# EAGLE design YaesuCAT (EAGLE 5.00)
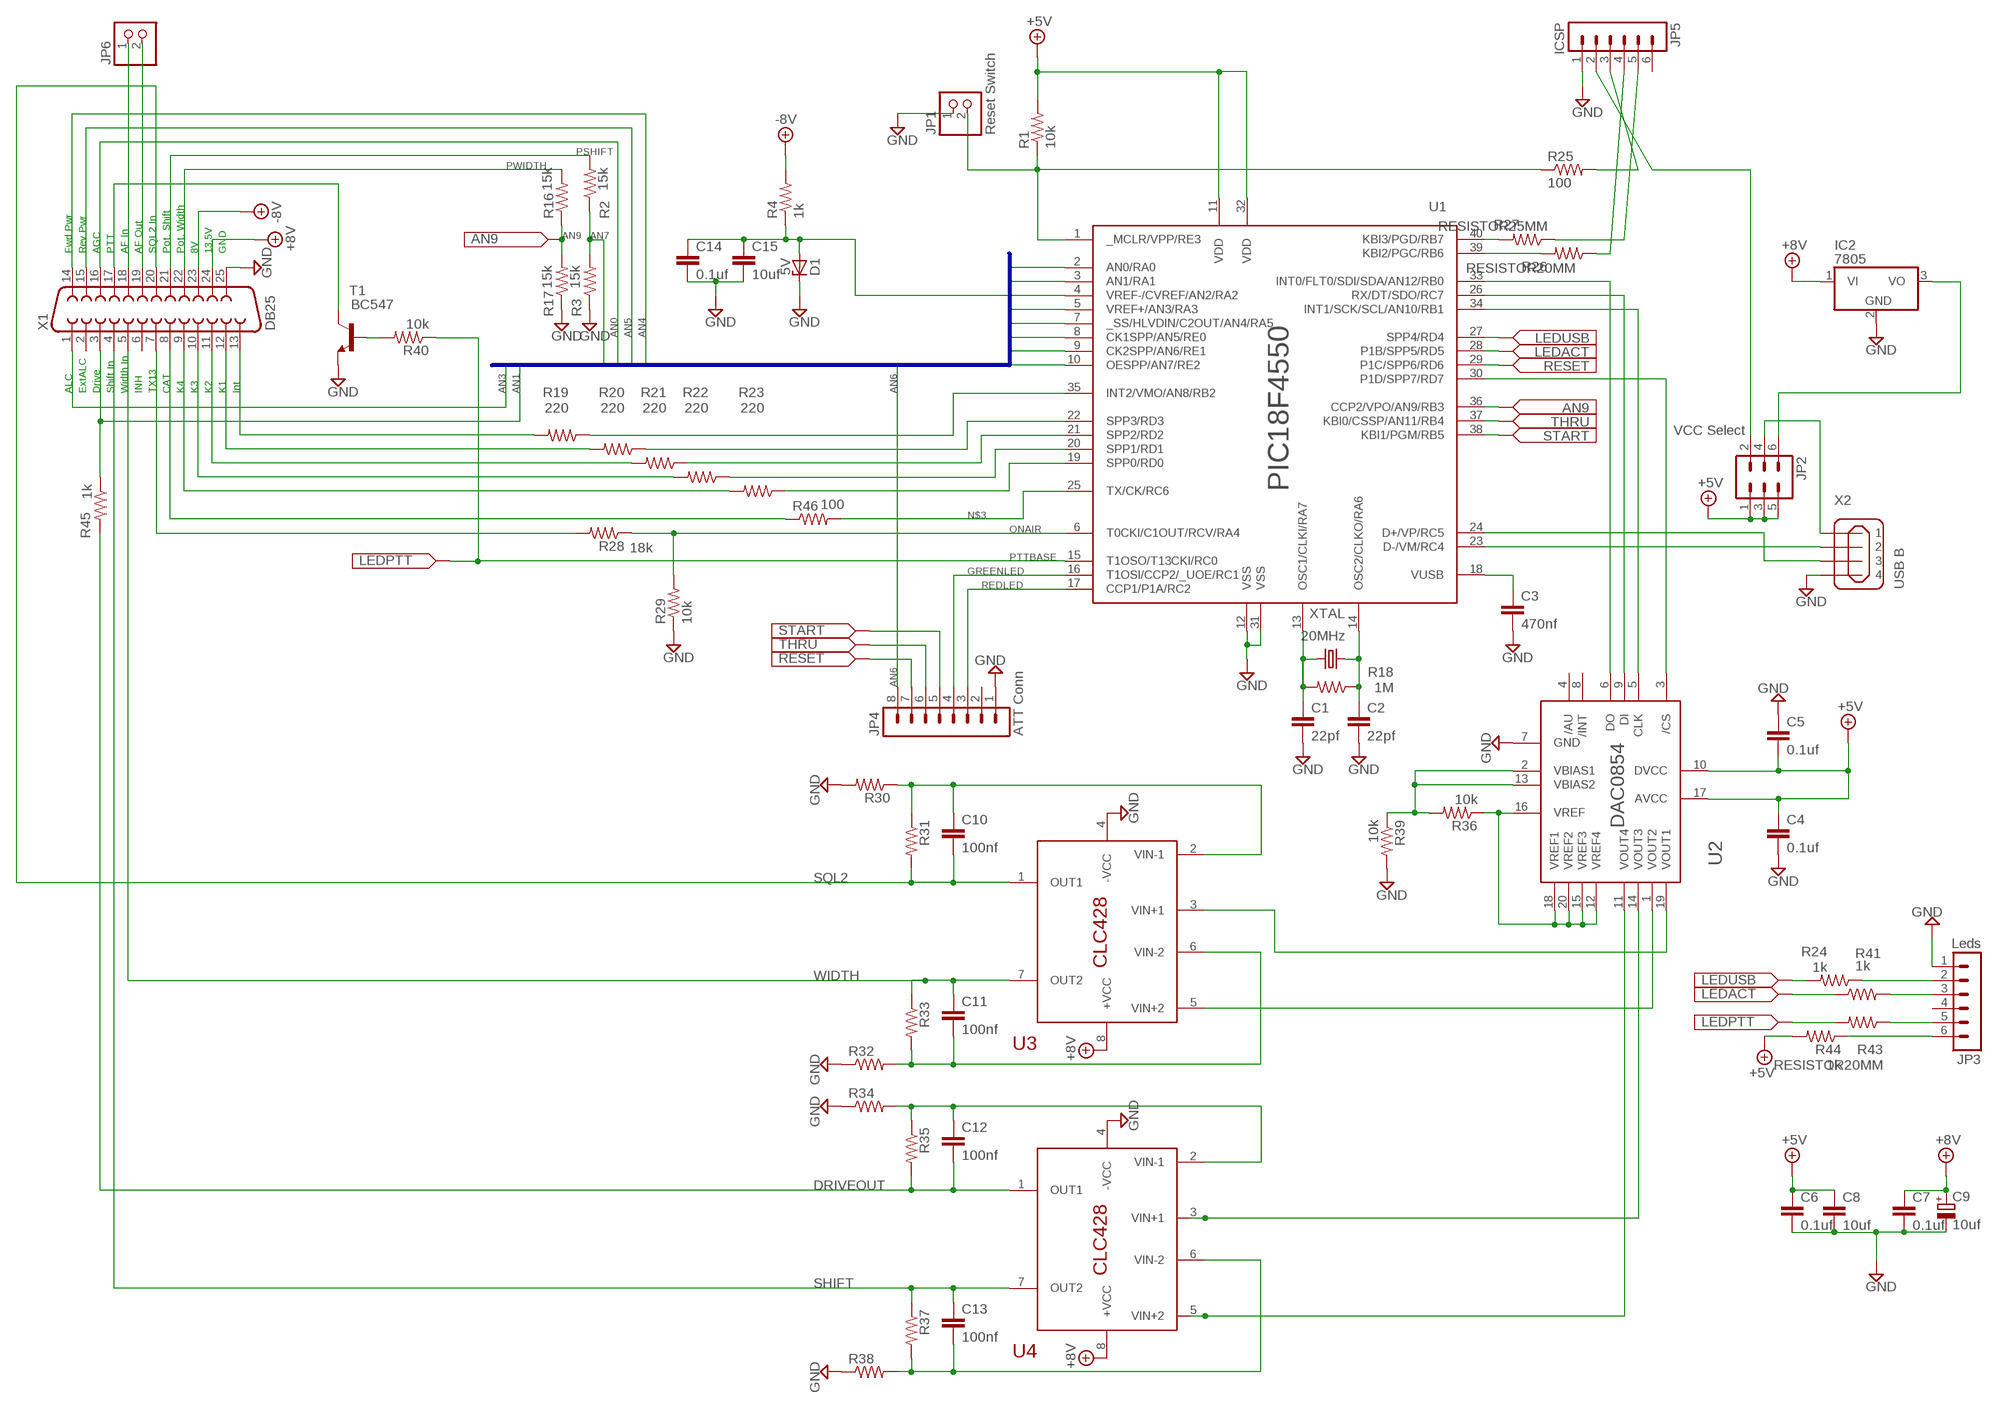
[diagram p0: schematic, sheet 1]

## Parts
C1  22pf  C-EU050-035X075  [C050-035X075]
C2  22pf  C-EU075-032X103  [C075-032X103]
C3  470nf  C-EU050-035X075  [C050-035X075]
C4  0.1uf  C-EU025-030X050  [C025-030X050]
C5  0.1uf  C-EU050-035X075  [C050-035X075]
C6  0.1uf  C-EU050-035X075  [C050-035X075]
C7  0.1uf  C-EU050-035X075  [C050-035X075]
C8  10uf  C-EU050-035X075  [C050-035X075]
C9  10uf  CPOL-EUE3.5-8  [E3,5-8]
C10  100nf  C-EU050-035X075  [C050-035X075]
C11  100nf  C-EU050-035X075  [C050-035X075]
C12  100nf  C-EU050-035X075  [C050-035X075]
C13  100nf  C-EU050-035X075  [C050-035X075]
C14  0.1uf  C-EU050-035X075  [C050-035X075]
C15  10uf  C-EU050-035X075  [C050-035X075]
D1  5V  ZENER-DIODEZD-7.5  [ZDIO-7.5]
IC2  7805  7805TV  [TO220V]
JP1  Reset Switch  PINHD-1X2  [1X02]
JP2  VCC Select  MA03-2  [MA03-2]
JP3  Leds  MA06-1  [MA06-1]
JP4  ATT Conn  MA08-1  [MA08-1]
JP5  ICSP  MA06-1  [MA06-1]
JP6  PINHD-1X2  [1X02]
R1  10k  R-US_0207/12  [0207/12]
R2  15k  R-US_0207/15  [0207/15]
R3  15k  R-US_0207/10  [0207/10]
R4  1k  R-US_0207/12  [0207/12]
R16  15k  R-US_0207/15  [0207/15]
R17  15k  R-US_0207/10  [0207/10]
R18  1M  R-US_0207/2V  [0207/2V]
R19  220  R-US_0207/10  [0207/10]
R20  220  R-US_0207/10  [0207/10]
R21  220  R-US_0207/10  [0207/10]
R22  220  R-US_0207/10  [0207/10]
R23  220  R-US_0207/15  [0207/15]
R24  1k  R-US_0207/10  [0207/10]
R25  100  R-US_0207/12  [0207/12]
R26  RESISTOR20MM  [R207/20MM]
R27  RESISTOR25MM  [R207/25MM]
R28  18k  R-US_0207/5V  [0207/5V]
R29  10k  R-US_0207/5V  [0207/5V]
R30  R-US_0207/10  [0207/10]
R31  R-US_0207/2V  [0207/2V]
R32  R-US_0207/2V  [0207/2V]
R33  R-US_0207/10  [0207/10]
R34  R-US_0207/10  [0207/10]
R35  R-US_0207/10  [0207/10]
R36  10k  R-US_0204/5  [0204/5]
R37  R-US_0207/2V  [0207/2V]
R38  R-US_0207/5V  [0207/5V]
R39  10k  R-US_0207/7  [0207/7]
R40  10k  R-US_0207/15  [0207/15]
R41  1k  R-US_0207/10  [0207/10]
R43  RESISTOR20MM  [R207/20MM]
R44  1k  R-US_0207/10  [0207/10]
R45  1k  R-US_0207/15  [0207/15]
R46  100  R-US_0207/10  [0207/10]
T1  BC547  [TO92]
U1  PIC18F4550  [DIP40]
U2  DAC0854  [DIP20]
U3  CLC428  [DIP8]
U4  CLC428  [DIP8]
X1  DB25  F25HP  [F25HP]
X2  USB B  MINI-USB_SHIELD4P-85-32004-00X  [85-32004-00X]
XTAL  20MHz  CRYSTALHC49U70  [HC49U70]

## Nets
+5V: C4.1 C5.2 C6.1 C8.1 JP2.1 JP2.3 JP2.5 R1.2 R44.2 U1.11(VDD) U1.32(VDD) U2.10(DVCC) U2.17(AVCC)
+8V: C7.1 C9.+ IC2.1(VI) U3.8(+VCC) U4.8(+VCC) X1.24
-8V: R4.2 X1.23
-VREF: C14.1 C15.1 D1.A R4.1 U1.4(VREF-/CVREF/AN2/RA2)
AN0: U1.2(AN0/RA0) X1.16
AN1: R45.1 U1.3(AN1/RA1) X1.3
AN3: U1.5(VREF+/AN3/RA3) X1.1
AN4: U1.7(_SS/HLVDIN/C2OUT/AN4/RA5) X1.14
AN5: U1.8(CK1SPP/AN5/RE0) X1.15
AN6: JP4.8 U1.9(CK2SPP/AN6/RE1)
AN7: R2.1 R3.2 U1.10(OESPP/AN7/RE2)
AN9: R16.1 R17.2 U1.36(CCP2/VPO/AN9/RB3)
CAT: R46.1 X1.8
CSDAC: U1.30(P1D/SPP7/RD7) U2.3(/CS)
D+: U1.24(D+/VP/RC5) X2.3
D-: U1.23(D-/VM/RC4) X2.2
DRIVEOUT: C12.2 R35.2 R45.2 U4.1(OUT1)
GND: C1.2 C2.2 C3.2 C4.2 C5.1 C6.2 C7.2 C8.2 C9.- C14.2 C15.2 D1.C IC2.2(GND) JP1.1 JP3.1 JP4.1 JP5.1 R3.1 R17.1 R29.1 R30.2 R32.1 R34.1 R38.1 R39.2 T1.1(E) U1.12(VSS) U1.31(VSS) U2.7(GND) U3.4(-VCC) U4.4(-VCC) X1.25 X2.4
GREENLED: JP4.4 U1.16(T1OSI/CCP2/_UOE/RC1)
INT: R19.2 X1.13
K1: R20.2 X1.12
K2: R21.2 X1.11
K3: R22.2 X1.10
K4: R23.2 X1.9
LEDACT: R41.1 U1.28(P1B/SPP5/RD5)
LEDUSB: R24.2 U1.27(SPP4/RD4)
N$1: JP1.2 R1.1 R25.1 U1.1(_MCLR/VPP/RE3)
N$2: JP5.4 R26.P$1
N$3: R46.2 U1.25(TX/CK/RC6)
N$5: JP6.1 X1.18
N$6: JP6.2 X1.19
N$10: R20.1 U1.22(SPP3/RD3)
N$11: R27.P$2 U1.40(KBI3/PGD/RB7)
N$12: R26.P$2 U1.39(KBI2/PGC/RB6)
N$13: R21.1 U1.21(SPP2/RD2)
N$14: JP5.5 R27.P$1
N$17: R19.1 U1.35(INT2/VMO/AN8/RB2)
N$20: JP5.3 R25.2
N$22: JP3.2 R24.1
N$23: JP3.3 R41.2
N$25: JP3.5 R43.P$1
N$30: JP3.6 R44.1
N$34: C1.1 R18.2 U1.13(OSC1/CLKI/RA7) XTAL.2
N$35: C2.1 R18.1 U1.14(OSC2/CLKO/RA6) XTAL.1
N$36: JP2.2 JP5.2
N$37: C3.1 U1.18(VUSB)
N$41: C13.2 R37.2 R38.2 U4.6(VIN-2)
N$42: C12.1 R34.2 R35.1 U4.2(VIN-1)
N$43: C11.2 R32.2 R33.2 U3.6(VIN-2)
N$44: C10.1 R30.1 R31.1 U3.2(VIN-1)
N$49: R40.2 T1.2(B)
N$50: U2.19(VOUT1) U3.3(VIN+1)
N$51: U2.1(VOUT2) U3.5(VIN+2)
N$52: U2.14(VOUT3) U4.3(VIN+1)
N$53: U2.11(VOUT4) U4.5(VIN+2)
N$54: U1.34(INT1/SCK/SCL/AN10/RB1) U2.5(CLK)
N$55: U1.26(RX/DT/SDO/RC7) U2.9(DI)
N$56: U1.33(INT0/FLT0/SDI/SDA/AN12/RB0) U2.6(DO)
N$58: R36.1 U2.12(VREF4) U2.15(VREF3) U2.16(VREF) U2.18(VREF1) U2.20(VREF2)
N$60: IC2.3(VO) JP2.6
ONAIR: R28.1 R29.2 U1.6(T0CKI/C1OUT/RCV/RA4)
PSHIFT: R2.2 X1.21
PTT: T1.3(C) X1.17
PTTBASE: R40.1 R43.P$2 U1.15(T1OSO/T13CKI/RC0) ; supply symbol labelled LEDPTT
PWIDTH: R16.2 X1.22
RD0: R23.1 U1.19(SPP0/RD0)
RD1: R22.1 U1.20(SPP1/RD1)
REDLED: JP4.3 U1.17(CCP1/P1A/RC2)
RESET: JP4.7 U1.29(P1C/SPP6/RD6)
SHIFT: C13.1 R37.1 U4.7(OUT2) X1.4
SQL2: C10.2 R31.2 U3.1(OUT1) X1.20
START: JP4.5 U1.38(KBI1/PGM/RB5)
THRU: JP4.6 U1.37(KBI0/CSSP/AN11/RB4)
TX13: R28.2 X1.7
USB+5V: JP2.4 X2.1
VBIAS: R36.2 R39.1 U2.2(VBIAS1) U2.13(VBIAS2)
WIDTH: C11.1 R33.1 U3.7(OUT2) X1.5
Unconnected: JP3.4 JP4.2 JP5.6 U2.4(/AU) U2.8(/INT) X1.2 X1.6 X2.M1(S1) X2.M2(S2)

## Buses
AN[0..7]

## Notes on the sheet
- Fwd Pwr | Rev Pwr | AGC | PTT | AF In | AF Out | SQL2 In | Pot. Shift | Pot. Width | 8V | 13.5V | GND
- ALC | ExtALC | Drive | Shift In | Width In | INH | TX13 | CAT | K4 | K3 | K2 | K1 | Int

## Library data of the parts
C1-C8 C10-C15 = resistor:C-EU: CAPACITOR, European symbol
C9 = resistor:CPOL-EU: POLARIZED CAPACITOR, European symbol
D1 = diode:ZENER-DIODE: Z-Diode
IC2 = linear:78*: Positive VOLTAGE REGULATOR Source: http://cache.national.com/ds/LM/LM78L05.pdf http://www.fairchildsemi.com/ds/LM/LM7805.pdf
JP1 JP6 = pinhead:PINHD-1X2: PIN HEADER
JP2 = con-lstb:MA03-2: PIN HEADER
JP3 JP5 = con-lstb:MA06-1: PIN HEADER
JP4 = con-lstb:MA08-1: PIN HEADER
R1-R4 R16-R25 R28-R41 R44-R46 = resistor:R-US_: RESISTOR, American symbol
R26 R27 R43 = components:RESISTOR
T1 = transistor:BC547: NPN TRANSISTOR
U1 = components:PIC18F4550: PIC18F4550 DIP-40 Specially arranged for schematics for the Yaesu FT-757GX Enhanced CAT interface schematics.
U2 = components:DAC0854: Quad 8-bit DAC. Controlled by SPI.
U3 U4 = components:CLC428: Dual wideband Op Amp
X1 = con-subd:F25: SUB-D
X2 = con-cypressindustries:MINI-USB_SHIELD4P-: MINI USB 4 Pol. Source: www.cypressindustries.com
XTAL = crystal:CRYSTAL: CRYSTAL

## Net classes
0 default: width 0.508 mm, drill 0.127 mm, clearance 0.381 mm

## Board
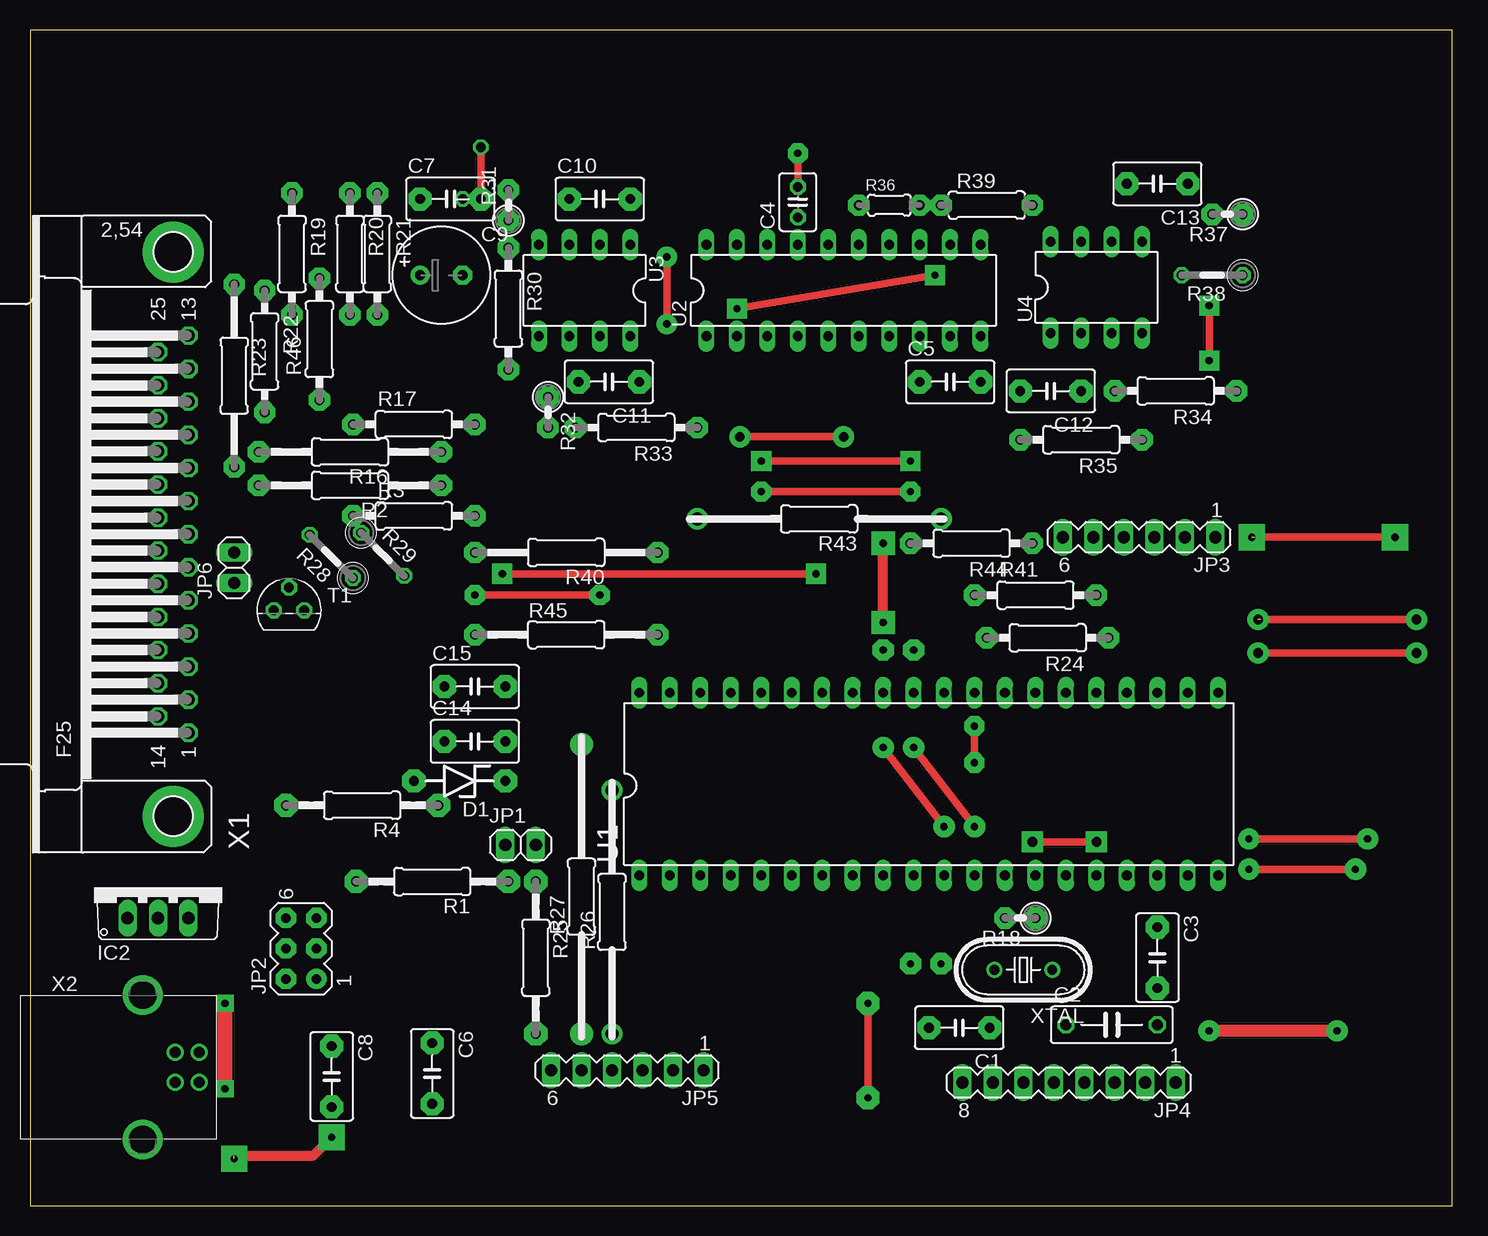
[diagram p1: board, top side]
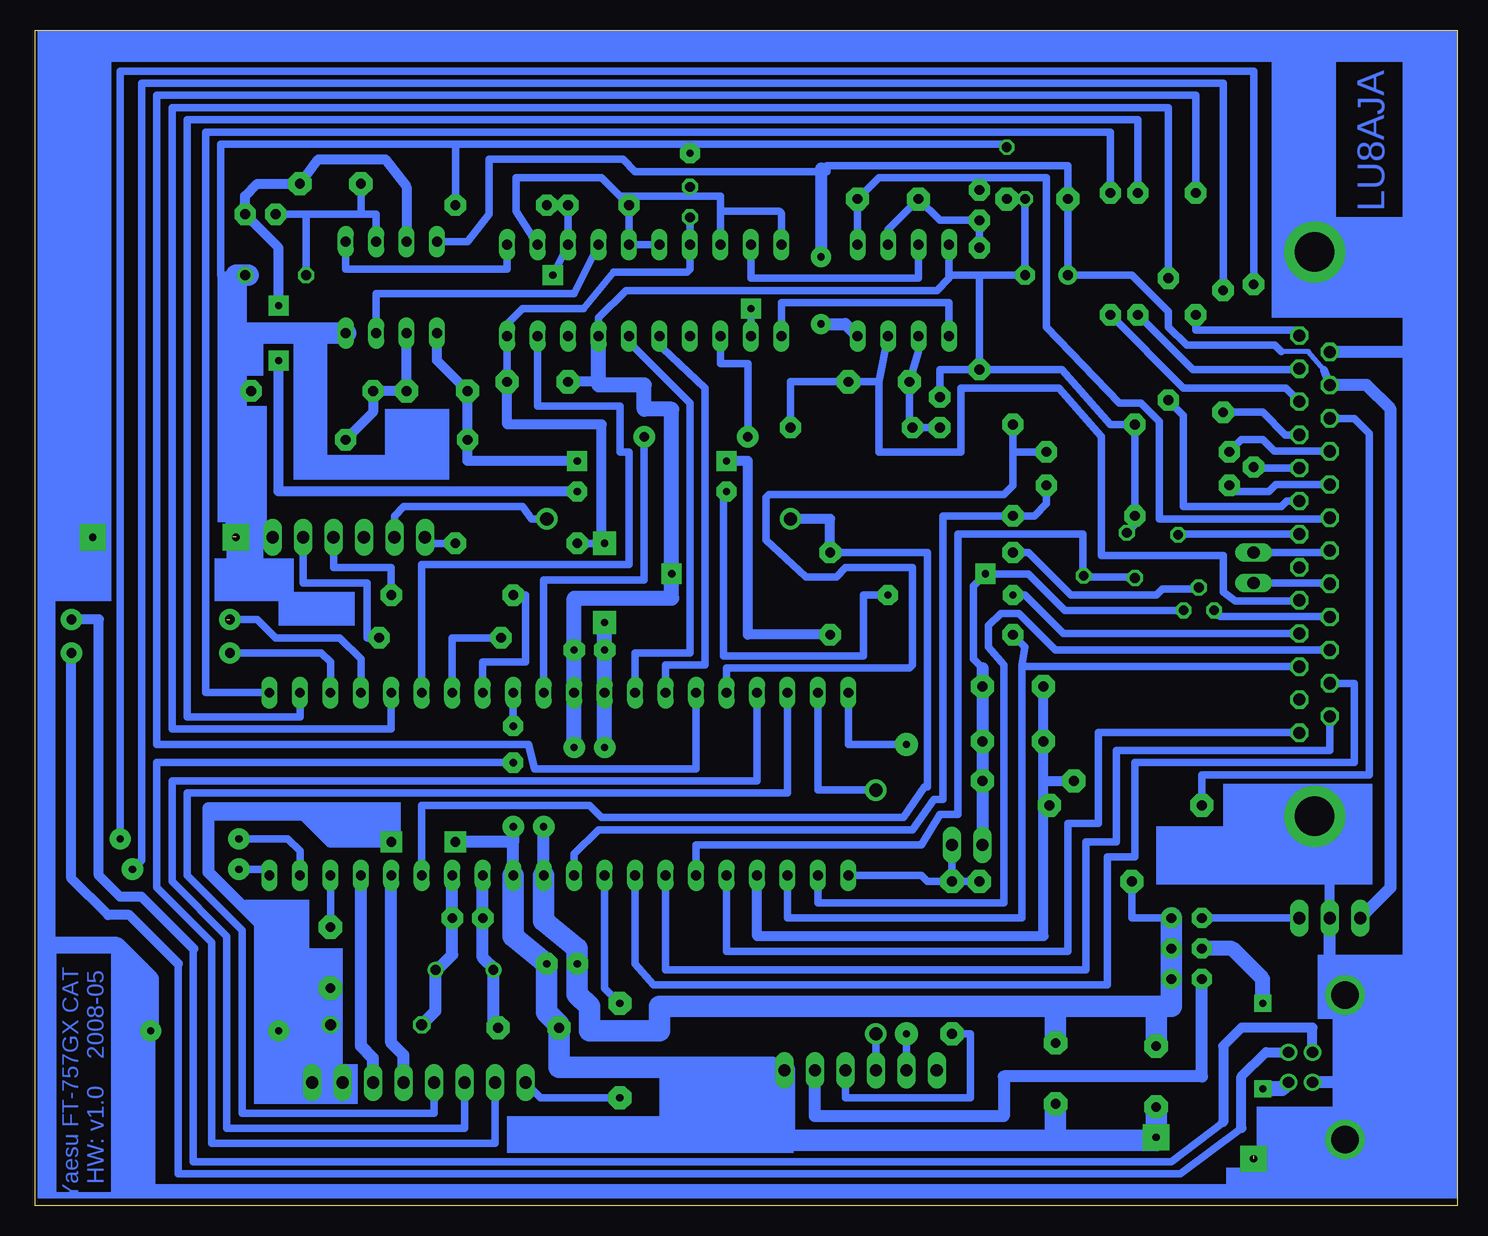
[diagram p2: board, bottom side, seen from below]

Size 118.54 x 98.03 mm. Coordinates in mm from the lower left corner, seen from the top.
Outline: 0,0 118.54,0 118.54,98.03 0,98.03 0,0
Copper layers (1*16): Top 0.035mm / dielectric 1.5mm / Bottom 0.035mm
Design rules "default *": minimum track width 20mil, minimum drill 5mil, track to track 8mil, track to pad 8mil, pad to pad 8mil, via to via 8mil, smd to smd 8mil, copper to edge 40mil, drill to drill 8mil, minimum pad ring 10mil, minimum via ring 8mil, stop-mask expansion 4mil, vias tented up to drill 20mil, thermal gap 10mil

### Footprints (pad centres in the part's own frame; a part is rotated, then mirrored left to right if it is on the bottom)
C050-035X075 = drill 0.813 pad 1.93 octagon: 1 -2.54,0; 2 2.54,0
C075-032X103 = drill 0.914 octagon: 1 -3.81,0; 2 3.81,0
C025-030X050 = drill 0.813 octagon: 1 -1.27,0; 2 1.27,0
E3,5-8 = drill 0.813 pad 1.6 round: + -1.778,0 | drill 0.813 pad 1.6 octagon: - 1.778,0
ZDIO-7.5 = drill 0.813 pad 1.93 octagon: A 3.81,0; C -3.81,0
TO220V = drill 1.016 long: 1 -2.54,-2.54; 2 0,-2.54; 3 2.54,-2.54
1X02 = drill 1.016 long: 1 -1.27,0; 2 1.27,0
MA03-2 = drill 0.8 pad 1.676 round: 1 -2.54,-1.27 | drill 0.8 pad 1.676 octagon: 2 -2.54,1.27; 3 0,-1.27; 4 0,1.27; 5 2.54,-1.27; 6 2.54,1.27
MA06-1 = drill 1.016 long: 1 -6.35,0; 2 -3.81,0; 3 -1.27,0; 4 1.27,0; 5 3.81,0; 6 6.35,0
MA08-1 = drill 1.016 long: 1 -8.89,0; 2 -6.35,0; 3 -3.81,0; 4 -1.27,0; 5 1.27,0; 6 3.81,0; 7 6.35,0; 8 8.89,0
0207/12 = drill 0.813 pad 1.93 octagon: 1 -6.35,0; 2 6.35,0
0207/15 = drill 0.813 pad 1.778 octagon: 1 -7.62,0; 2 7.62,0
0207/10 = drill 0.813 pad 1.778 octagon: 1 -5.08,0; 2 5.08,0
0207/2V = drill 0.813 pad 1.778 octagon: 1 -1.27,0; 2 1.27,0
R207/20MM = drill 1.1 pad 1.778 round: P$1 -10.16,0; P$2 10.16,0
R207/25MM = drill 0.6 pad 1.93 round: P$1 -11.43,0; P$2 12.7,0
0207/5V = drill 0.813 octagon: 1 -2.54,0; 2 2.54,0
0204/5 = drill 0.813 pad 1.778 octagon: 1 -2.54,0; 2 2.54,0
0207/7 = drill 0.813 pad 1.778 octagon: 1 -3.81,0; 2 3.81,0
TO92 = drill 0.813 octagon: 1 1.27,0; 2 0,1.905; 3 -1.27,0
DIP40 = drill 0.813 long: 1 -24.13,-8.89; 2 -21.59,-8.89; 3 -19.05,-8.89; 4 -16.51,-8.89; 5 -13.97,-8.89; 6 -11.43,-8.89; 7 -8.89,-8.89; 8 -6.35,-8.89; 9 -3.81,-8.89; 10 -1.27,-8.89; 11 1.27,-8.89; 12 3.81,-8.89; 13 6.35,-8.89; 14 8.89,-8.89; 15 11.43,-8.89; 16 13.97,-8.89; 17 16.51,-8.89; 18 19.05,-8.89; 19 21.59,-8.89; 20 24.13,-8.89; 21 24.13,6.35; 22 21.59,6.35; 23 19.05,6.35; 24 16.51,6.35; 25 13.97,6.35; 26 11.43,6.35; 27 8.89,6.35; 28 6.35,6.35; 29 3.81,6.35; 30 1.27,6.35; 31 -1.27,6.35; 32 -3.81,6.35; 33 -6.35,6.35; 34 -8.89,6.35; 35 -11.43,6.35; 36 -13.97,6.35; 37 -16.51,6.35; 38 -19.05,6.35; 39 -21.59,6.35; 40 -24.13,6.35
DIP20 = drill 0.813 long: 1 -11.43,-3.81; 2 -8.89,-3.81; 3 -6.35,-3.81; 4 -3.81,-3.81; 5 -1.27,-3.81; 6 1.27,-3.81; 7 3.81,-3.81; 8 6.35,-3.81; 9 8.89,-3.81; 10 11.43,-3.81; 11 11.43,3.81; 12 8.89,3.81; 13 6.35,3.81; 14 3.81,3.81; 15 1.27,3.81; 16 -1.27,3.81; 17 -3.81,3.81; 18 -6.35,3.81; 19 -8.89,3.81; 20 -11.43,3.81
DIP8 = drill 0.813 long: 1 -3.81,-3.81; 2 -1.27,-3.81; 3 1.27,-3.81; 4 3.81,-3.81; 5 3.81,3.81; 6 1.27,3.81; 7 -1.27,3.81; 8 -3.81,3.81
F25HP = drill 1.016 octagon: 1 -16.561,-1.27; 2 -13.792,-1.27; 3 -11.049,-1.27; 4 -8.28,-1.27; 5 -5.512,-1.27; 6 -2.769,-1.27; 7 0,-1.27; 8 2.769,-1.27; 9 5.512,-1.27; 10 8.28,-1.27; 11 11.049,-1.27; 12 13.792,-1.27; 13 16.561,-1.27; 14 -15.189,1.27; 15 -12.421,1.27; 16 -9.652,1.27; 17 -6.909,1.27; 18 -4.14,1.27; 19 -1.372,1.27; 20 1.372,1.27; 21 4.14,1.27; 22 6.909,1.27; 23 9.652,1.27; 24 12.421,1.27; 25 15.189,1.27 | drill 3.302 pad 5.08 round: G1 -23.52,0; G2 23.52,0
85-32004-00X = drill 0.92 pad 1.27 round: 1 4.71,-1.25; 2 4.71,1.25; 3 2.71,1.25; 4 2.71,-1.25 | drill 2.3 pad 3 round: M1 0,6.02; M2 0,-6.02
HC49U70 = drill 0.813 round: 1 -2.413,0; 2 2.413,0

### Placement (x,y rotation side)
C1  77.43,14.85 180 top
C2  90.13,15.11 0 top
C3  93.94,20.7 270 top
C4  63.97,83.69 90 top
C5  76.67,68.7 0 top
C6  33.49,11.04 270 top
C7  35.01,83.94 0 top
C8  25.11,10.79 270 top
C9  34.25,77.59 0 top
C10  47.46,83.94 0 top
C11  48.22,68.7 180 top
C12  85.05,67.94 180 top
C13  93.94,85.21 180 top
C14  37.05,38.73 0 top
C15  37.05,43.3 0 top
D1  35.78,35.43 180 top
IC2  10.63,26.54 0 top
JP1  40.86,30.09 0 top
JP2  22.57,21.46 90 top
JP3  92.42,55.75 180 top
JP4  86.58,10.28 180 top
JP5  49.75,11.3 180 top
JP6  16.98,53.21 90 top
R1  33.49,27.05 180 top
R2  26.63,60.07 180 top
R3  31.97,57.53 0 top
R4  27.65,33.4 180 top
R16  26.63,62.86 180 top
R17  31.97,65.15 0 top
R18  82.51,24 180 top
R19  21.81,79.37 270 top
R20  26.63,79.37 270 top
R21  28.92,79.37 270 top
R22  19.52,71.24 270 top
R23  16.98,69.21 270 top
R24  84.8,47.37 180 top
R25  42.13,20.7 270 top
R26  48.48,24.51 90 top
R27  45.94,25.78 90 top
R28  25.08,54.15 135 top
R29  29.35,54.33 315 top
R30  39.84,74.8 270 top
R31  39.84,83.43 90 top
R32  43.14,66.16 270 top
R33  50.51,64.89 180 top
R34  95.47,67.94 180 top
R35  87.59,63.88 180 top
R36  71.59,83.43 0 top
R37  99.78,82.67 180 top
R38  98.51,77.59 180 top
R39  79.72,83.43 0 top
R40  44.67,54.48 180 top
R41  83.78,50.92 0 top
R43  65.75,57.27 180 top
R44  78.45,55.24 180 top
R45  44.67,47.62 0 top
R46  24.09,72.26 90 top
T1  21.55,49.65 0 top
U1  74.89,36.44 0 top
U2  67.78,76.32 0 top
U3  46.19,76.32 180 top
U4  88.86,76.58 0 top
X1  11.9,56 90 top
X2  9.36,11.55 0 top
XTAL  82.77,19.68 180 top

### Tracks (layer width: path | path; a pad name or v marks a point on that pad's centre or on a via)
+5V  (via drill 0.6 pad 1.78, 0.6 pad 1.93)
  Top 0.61: v76.16,31.62 v71.08,38.22
  Top 0.813: v71.08,48.64 v71.08,55.24
  Bottom 0.61: C5.2 U2.10 79.21,73.53 77.94,74.8 72.86,74.8 70.32,77.85 64.22,77.85 63.97,78.1 U2.17 C4.1 | v71.08,55.24 R44.2 | R1.2 27.14,24 JP2.5
  Bottom 0.813: v71.08,55.24 71.34,55.24 71.34,65.15 79.21,65.15 C5.2
  Bottom 1.016: U1.11 v76.16,31.62
  Bottom 1.27: v71.08,38.22 U1.32 v71.08,46.35 v71.08,48.64
  Bottom 1.778: JP2.5 JP2.3 JP2.1 | JP2.1 23.84,18.66 | JP2.1 23.84,16.63 25.11,16.63 | 25.11,16.63 33.49,16.63 | 33.49,16.63 66.51,16.63 66.51,14.6 72.35,14.6 72.35,16.63 73.37,17.65 v73.37,20.19 73.37,21.46 76.16,23.74 U1.11 | C8.1 25.11,16.63 | 33.49,16.63 C6.1
+8V  (via drill 0.6 pad 1.68)
  Top 0.61: v53.05,79.12 v53.05,73.53
  Bottom 0.406: 11.14,69.72 12.41,71.24 14.69,71.24
  Bottom 0.61: U4.8 82.51,80.39 80.73,82.67 80.73,87.24 69.56,87.24 68.54,86.23 53.05,86.23 52.54,86.23 52.54,86.74 32.47,86.74 C7.1 C9.+ 27.14,77.59 24.09,74.54 24.09,73.27 22.57,71.75 15.2,71.75 14.69,71.24 | X1.24 11.14,69.72
  Bottom 1.016: U3.8 51.02,73.53 v53.05,73.53 | 53.05,86.48 53.05,86.23 v53.05,79.12 | IC2.1 5.55,26.54 5.55,66.42 7.58,68.45 10.63,68.45 X1.24
-8V
  Bottom 0.61: R4.2 21.3,35.94 7.33,35.94 7.33,64.38 8.6,65.65 X1.23
-VREF
  Bottom 0.813: U1.4 58.38,22.47 34.51,22.47 34.51,33.4 | C14.1 34.51,38.48 | C14.1 C15.1 | 34.51,35.43 C14.1 | 34.51,35.43 D1.A | 34.51,33.4 34.51,35.43 | 34.51,33.4 R4.1
AN0
  Bottom 0.61: U1.2 53.3,25.27 37.81,25.27 37.81,45.08 39.08,46.6 39.08,48.38 38.06,49.4 36.54,49.4 33.49,46.35 X1.16
AN1
  Bottom 0.61: U1.3 55.84,24 36.28,24 36.28,45.08 | 36.28,45.08 36.03,46.6 R45.1 | X1.3 35.9,44.95 36.28,45.08
AN3
  Bottom 0.61: U1.5 60.92,21.2 32.47,21.2 32.47,31.87 29.93,31.87 29.93,39.49 13.17,39.49 X1.1
AN4
  Bottom 0.61: U1.7 66,19.68 30.95,19.68 30.95,30.35 28.41,30.35 28.41,37.97 10.63,37.97 X1.14
AN5
  Bottom 0.61: U1.8 68.54,20.19 67.02,18.41 29.17,18.41 29.17,29.08 26.89,29.08 26.89,36.95 8.6,36.95 8.6,43.56 10.63,43.56 X1.15
AN6  (via drill 0.6 pad 1.93)
  Top 0.61: v69.81,9.01 v69.81,16.89
  Bottom 0.61: JP4.8 76.42,9.01 v69.81,9.01 | v69.81,16.89 71.08,18.16 U1.9
AN7
  Bottom 0.61: R2.1 34.25,58.54 35.27,57.53 R3.2 42.89,57.53 42.89,33.9 43.65,33.9 45.43,31.36 71.59,31.36 73.62,29.33 U1.10
AN9
  Bottom 0.61: 37.05,62.86 R17.2 | 37.05,62.86 R16.1 | 37.05,62.86 37.05,60.07 37.81,59.3 57.37,59.3 57.62,59.05 57.62,55.49 54.32,52.45 51.78,52.45 51.02,53.21 45.43,53.21 45.43,45.08 45.68,44.83 60.92,44.83 U1.36
CAT
  Bottom 0.61: X1.8 14.21,58.77 14.69,58.29 22.82,58.29 22.82,65.91 R46.1
CSDAC  (via drill 0.8 pad 1.78)
  Top 0.61: v67.78,64.13 v59.14,64.13
  Bottom 0.61: U1.30 76.16,52.19 67.78,52.19 v67.78,64.13 | U2.3 61.43,70.23 59.14,70.23 v59.14,64.13
D+  (via drill 0.8 pad 1.78)  (1 unrouted)
  Top 0.61: v115.53,48.89 102.58,48.89
  Bottom 0.61: v102.32,48.89 100.04,48.89 98.51,47.37 93.18,47.37 91.4,45.59 U1.24 | 19.52,6.98 23.84,3.68 105.37,3.68 105.37,21.46
  Bottom 0.813: X2.3 12.09,14.85 18,14.85 19.52,13.33 19.52,6.98 | 105.37,21.46 109.69,25.78 111.47,25.78 113.25,27.55 113.25,48.89 v115.53,48.89
D-  (via drill 0.8 pad 1.78)
  Top 0.61: v115.53,46.1 v102.32,46.1
  Bottom 0.61: v102.32,46.1 94.7,46.1 93.94,45.33 U1.23 93.94,42.54 | 18,6.47 23.08,2.66 106.64,2.66 106.64,20.19
  Bottom 0.813: X2.2 15.96,12.82 18,10.79 18,6.47 | 106.64,20.19 110.71,24.25 112.48,24.25 115.53,27.3 v115.53,46.1
DRIVEOUT  (via drill 0.6 pad 1.68)
  Top 0.61: v60.92,62.1 v73.37,62.1
  Bottom 0.61: R35.2 82.77,63.88
  Bottom 0.813: R45.2 59.14,47.62 59.14,62.1 v60.92,62.1 | 82.51,64.13 R35.2 | v73.37,62.1 82.51,62.1 82.51,64.13 | 82.51,64.13 C12.2 85.05,70.48 U4.1
GND  (via drill 0.6 pad 1.68, 0.6 pad 1.78, 0.6 pad 2.18, 0.8 pad 1.27, 0.8 pad 1.78)  (2 unrouted)
  Top 0.61: v83.53,30.35 v88.86,30.35 | v78.7,31.62 v73.62,38.22 | 102.07,55.75 v113.75,55.75 | v63.97,87.75 C4.2 | C7.2 v37.55,88.26 | v65.49,52.7 v39.33,52.7
  Top 0.813: 16.98,4.19 23.58,4.19 v25.11,5.71
  Top 1.016: v108.93,14.6 98.51,14.6
  Bottom 0.61: R30.2 39.84,71.24 | 39.84,77.59 R30.2 | 39.84,77.59 C9.- v36.03,83.94 C7.2 | 42.38,77.59 U3.4 | 42.38,77.59 39.84,77.59 | R30.2 32.98,69.72 28.92,65.15 R17.1 R3.1 26.89,56.79 R29.1 | 83.53,88.51 R39.2 | 83.53,88.51 103.09,88.51 103.09,77.59 R38.1 | R30.2 43.14,69.72 R32.1 | v37.55,88.26 37.81,88.51 63.97,88.51 | 63.97,88.51 83.53,88.51 | 63.97,88.51 v63.97,87.75 | U2.7 71.59,74.04 69.3,76.32 43.4,76.32 42.38,77.34 42.38,77.59 | T1.1 32.73,49.65 35.78,52.7 v39.33,52.7 40.35,51.68 40.35,45.59 39.59,44.83 | D1.C JP1.1
  Bottom 0.813: 4.03,17.65 4.03,5.46 4.03,1.39 108.93,1.39 v108.93,14.6 | 71.59,68.7 C5.1 | 10.63,23.74 10.63,28.06
  Bottom 1.016: X1.25 4.03,71.19 4.03,17.65 9.36,17.65 10.63,18.92 10.63,23.74 IC2.2 | v88.86,30.35 93.94,30.35 96.74,33.14 104.1,33.14 104.1,27.81 99.28,22.98 98.26,22.98 v98.26,14.6 95.72,14.6 | v83.53,30.35 78.7,30.35 v78.7,31.62 U1.12 | 95.72,14.6 95.47,14.6 JP4.1 | X2.4 9.36,10.3 9.36,5.46 4.03,5.46 | C3.2 C2.2 94.96,15.11 95.72,14.35 95.72,14.6 | 39.59,44.83 C15.2 C14.2 D1.C JP1.1
  Bottom 1.27: v73.62,38.22 U1.31 v73.62,46.35 73.62,50.67 65.49,50.67 v65.49,52.7 65.49,66.42 67.78,66.42 67.78,68.45 71.59,68.45 71.59,68.7 U2.7
  Bottom 1.422: v108.93,14.6 108.93,18.92 111.72,21.71 117.56,21.71 117.56,95.12 | v113.75,55.75 117.31,55.75 | v101.82,55.75 JP3.1
  Bottom 1.778: U1.12 78.7,22.47 v75.91,20.19 75.91,16.12 74.89,15.11 C1.2 74.89,11.55 57.11,11.55 JP5.1 56.1,5.46 33.49,5.46 | 33.49,5.46 25.11,5.46 v25.11,5.71 C8.2 | 33.49,5.46 C6.2 | 100.8,77.59 R38.1 101.82,77.59 101.82,72.77 | 101.82,72.77 101.82,67.94 | 101.82,67.94 v101.82,55.75 | 101.82,67.94 R34.1 | 101.82,72.77 U4.4 | v16.98,3.93 10.88,3.93 9.36,5.46
GREENLED
  Bottom 1.016: U1.16 88.86,13.58 87.85,12.57 JP4.4
INT
  Bottom 0.61: X1.13 13.63,73.02 21.81,73.02 R19.2
K1
  Bottom 0.61: X1.12 13.17,69.72 22.06,69.72 R20.2
K2
  Bottom 0.61: X1.11 14.31,68.19 22.82,68.19 R21.2
K3
  Bottom 0.61: X1.10 14.34,64.28 16.22,66.16 R22.2
K4
  Bottom 0.61: X1.9 16.14,61.51 R23.2
LEDACT
  Bottom 0.61: U1.28 81.24,45.33 77.69,45.33 77.69,50.92 R41.1
LEDUSB
  Bottom 0.61: 83.78,42.54 U1.27 83.78,47.37 R24.2
N$1
  Bottom 0.61: R25.1 44.16,27.05 44.67,27.55 U1.1 | R25.1 JP1.2 | R1.1 R25.1
N$2
  Bottom 0.61: JP5.4 R26.P$1
N$3
  Bottom 0.61: R46.2 24.09,91.56 107.15,91.56 107.15,39.75 88.86,39.75 U1.25
N$5
  Bottom 0.61: X1.18 10.63,51.94 JP6.1
N$6
  Bottom 0.61: X1.19 10.63,54.48 JP6.2
N$10
  Bottom 0.61: R20.1 26.63,90.55 105.88,90.55 105.88,40.76 96.48,40.76 U1.22
N$11
  Bottom 0.61: U1.40 50.76,38.48 R27.P$2
N$12
  Bottom 0.61: U1.39 53.3,34.67 R26.P$2
N$13
  Bottom 0.61: R21.1 28.92,89.53 104.36,89.53 104.36,42.79 U1.21
N$14
  Bottom 0.61: JP5.5 R27.P$1
N$17
  Bottom 0.61: R19.1 21.81,92.58 108.42,92.58 108.42,38.48 77.43,38.48 76.92,36.44 63.46,36.44 U1.35
N$20
  Bottom 0.61: R25.2 40.6,14.35 40.6,9.01 51.02,9.01 JP5.3
N$22
  Bottom 0.61: JP3.2 96.23,51.94 90.89,51.94 90.89,47.37 R24.1
N$23
  Bottom 0.61: JP3.3 93.69,53.21 88.86,53.21 R41.2
N$25
  Bottom 0.61: R43.P$1 77.18,57.27 77.94,58.29 87.85,58.29 88.61,57.53 88.61,56 88.86,55.75 JP3.5
N$30
  Bottom 0.61: JP3.6 86.32,55.75 arc-90 85.81,55.24 R44.1
N$34
  Bottom 1.016: U1.13 R18.2 81.24,20.7 80.23,19.68 XTAL.2 80.35,15.24 C1.1
N$35
  Bottom 1.016: U1.14 R18.1 83.78,20.95 85.05,19.68 XTAL.1 85.18,16.25 C2.1
N$36
  Bottom 1.016: JP2.2 21.3,10.79 37.81,10.79 37.81,7.49 53.56,7.49 JP5.2
N$37
  Bottom 0.61: C3.1 U1.18
N$41
  Bottom 0.61: 91.4,82.67 95.72,82.67 | 95.72,82.67 R37.2 | 91.4,82.67 C13.2 | U4.6 90.13,82.67 91.4,82.67 | R38.2 95.97,82.67 95.72,82.67
N$42
  Bottom 0.813: R35.1 90.39,66.16 R34.2 C12.1 U4.2
N$43
  Bottom 0.61: U3.6 44.92,71.24 C11.2 45.68,65.91 45.68,65.15 R33.2 R32.2
N$44
  Bottom 0.61: U3.2 47.46,81.4 C10.1 43.14,82.16 R31.1 R30.1
N$49
  Bottom 0.61: T1.2 21.55,51.43 24.6,51.43 25.11,50.92 32.22,50.92 35.78,54.48 R40.2
N$50
  Bottom 0.61: U2.19 58.89,77.34 44.92,77.34 U3.3
N$51
  Bottom 0.61: U3.5 42.38,75.31 56.35,75.31 56.35,72.26 U2.1
N$52
  Bottom 0.61: U2.14 73.62,76.07 90.13,76.07 U4.3 90.13,72.51
N$53
  Bottom 0.61: U2.11 79.21,78.1 92.67,78.1 U4.5
N$54
  Bottom 0.61: U1.34 66,45.08 62.7,45.08 62.7,68.19 66.26,71.5 66.51,71.75 U2.5
N$55
  Bottom 0.61: U1.26 86.32,53.46 69.05,53.46 69.05,62.86 69.81,62.86 69.81,66.67 76.67,66.67 U2.9 76.67,72.77
N$56
  Bottom 0.61: U1.33 68.54,46.1 63.97,46.1 63.97,66.92 69.05,72 U2.6
N$58
  Bottom 0.61: U2.20 56.35,82.67 arc-90 56.6,82.93 61.43,82.93 U2.18 61.43,84.2 69.81,84.2 69.69,84.07 | U2.12 78.45,82.93 78.45,85.72 71.34,85.72 69.69,84.07 | 69.69,84.07 69.3,83.43 R36.1 U2.15 U2.16
N$60
  Bottom 0.61: IC2.3 JP2.6
ONAIR
  Bottom 0.61: U1.6 63.46,30.09 44.67,30.09 43.14,32.63 41.62,32.63 41.62,56 31.2,56 31.2,52.47 | 26.97,52.45 R28.1 26.89,52.37 26.89,52.45 31.07,52.45 R29.2 31.2,52.47 | 31.2,52.47 31.2,52.45
PSHIFT
  Bottom 0.61: X1.21 15.13,60.14 15.71,59.56 18.5,59.56 R2.2
PTT
  Bottom 0.61: X1.17 10.63,49.14 19.77,49.14 T1.3
PTTBASE
  Bottom 0.61: R40.1 44.16,54.48 44.16,34.92 44.41,34.92 46.19,32.38 71.34,32.38 72.35,33.4 86.32,33.4 U1.15
  Bottom 0.813: R40.1 52.29,57.27 R43.P$2
PWIDTH
  Bottom 0.61: X1.22 15.25,62.91 16.22,63.88 18,63.88 R16.2
RD0  (via drill 0.6 pad 1.78)
  Top 0.61: v111.47,30.6 v101.56,30.6
  Bottom 0.61: R23.1 16.98,94.61 111.47,94.61 v111.47,30.6 | U1.19 96.48,29.59 97.5,30.6 v101.56,30.6
RD1  (via drill 0.6 pad 1.78)
  Top 0.61: v110.45,28.06 v101.56,28.06
  Bottom 0.61: R22.1 19.52,93.59 109.69,93.59 109.69,28.82 v110.45,28.06 | U1.20 99.53,28.06 v101.56,28.06
REDLED
  Bottom 1.016: U1.17 91.4,13.33 90.39,12.31 JP4.3
RESET  (via drill 0.6 pad 1.68)
  Top 0.61: v78.7,36.95 v78.7,40
  Bottom 0.61: JP4.7 80.23,5.2 103.85,5.2 103.85,21.97 108.42,26.54 108.42,36.95 v78.7,36.95 | v78.7,40 U1.29
SHIFT  (via drill 0.6 pad 1.68)
  Top 0.61: v60.92,59.56 v73.37,59.56 | v37.05,50.92 v47.46,50.92 | v98.26,70.48 v98.26,75.05
  Bottom 0.61: v47.46,50.92 49.49,50.92 49.49,45.84 61.18,45.84 61.18,59.3 | X1.4 32.83,47.72 36.03,50.92 v37.05,50.92
  Bottom 0.813: U4.7 87.59,84.96 89.37,87.24 94.96,87.24 C13.1 100.04,85.21 101.05,84.2 R37.1 98.26,79.88 v98.26,75.05 | 61.18,59.3 v60.92,59.56 | v73.37,59.56 98.26,59.56 v98.26,70.48
SQL2
  Bottom 0.61: U3.1 C10.2 48.22,85.72 39.84,85.72 | 39.84,85.72 R31.2 | 39.84,85.72 34.25,85.72 34.25,73.27 28.16,66.92 26.38,66.92 24.85,65.4 24.85,57.27 10.63,57.27 X1.20 10.63,57.53
START
  Bottom 0.61: U1.38 55.84,34.41 105.88,34.41 105.88,27.55 101.31,22.98 101.31,7.74 85.31,7.74 JP4.5
THRU
  Bottom 0.61: U1.37 58.38,35.43 107.15,35.43 107.15,27.05 102.58,22.47 102.58,6.47 82.77,6.47 JP4.6
TX13
  Bottom 0.61: R28.2 23.33,56 X1.7
USB+5V  (via drill 0.6 pad 1.42)
  Top 1.27: v16.22,9.77 v16.22,16.89
  Bottom 1.27: X2.1 14.6,9.77 v16.22,9.77 | JP2.4 18.76,21.46 16.22,18.92 v16.22,16.89
VBIAS  (via drill 0.6 pad 1.68)
  Top 0.61: v58.89,74.8 v75.4,77.59
  Bottom 0.61: U2.2 v58.89,74.8 | v75.4,77.59 U2.13 R36.2 R39.1
WIDTH
  Bottom 0.61: 48.22,68.7 C11.1 55.59,68.7 R33.1 | 48.22,68.7 U3.7 | X1.5 13.25,50.41 18.5,50.41 19.52,51.18 19.52,54.22 29.68,54.22 29.68,64.13 33.24,68.19 41.36,68.19 41.36,62.86 48.22,62.86 48.22,68.7
(copper drawn outside any net)
  shapes: Bottom area x43

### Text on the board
Top: Yaesu FT-757GX Enhanced USB CAT Interface
Bottom: LU8AJA | 2008-05 | Yaesu FT-757GX CAT | HW: v1.0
